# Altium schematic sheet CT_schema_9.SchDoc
size 147 x 119 mm
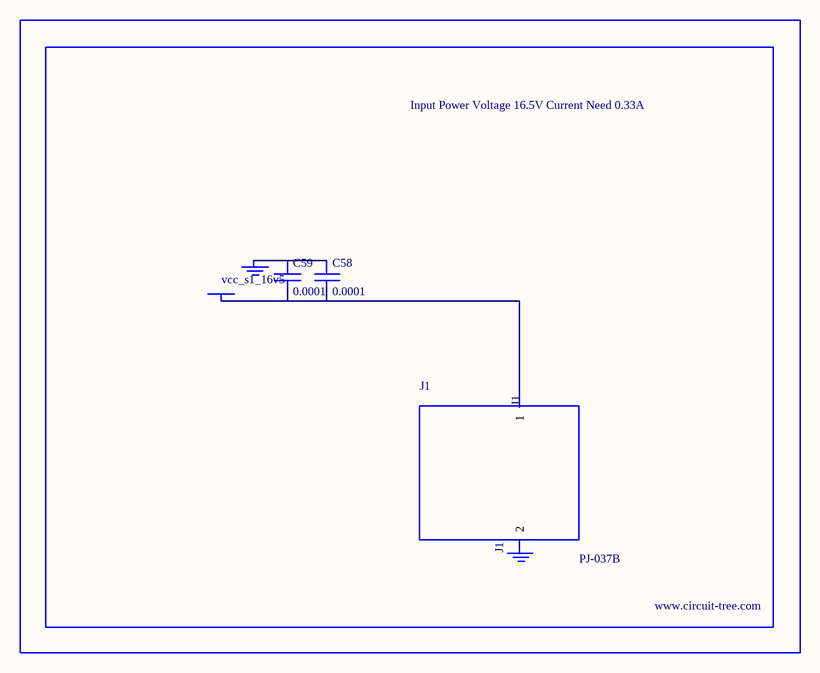
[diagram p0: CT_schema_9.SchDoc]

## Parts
BORDER8  (no value)
C58  0.0001  [EXV-9H]
C59  0.0001  [EXV-9H]
GND_INSTANCE_8_0  (no value)
GND_INSTANCE_8_1  (no value)
J1  PJ-037B  [PJ-037B_PACKAGE]
POWER_INSTANCE_8_0  vcc_s1_16v5

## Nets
NetC58_1: C58.1 C59.1 GND_INSTANCE_8_0.0(GND)
NetC58_2: C58.2 C59.2 J1.1 POWER_INSTANCE_8_0.0(PWR)

Not connected (* = marked no-connect by the designer): GND_INSTANCE_8_1 0(GND); J1 2

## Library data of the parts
BORDER8 = BORDER_PAGE8
C58 C59 = EDK107M035A9HAA
GND_INSTANCE_8_0 GND_INSTANCE_8_1 = GND
POWER_INSTANCE_8_0 = PWR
